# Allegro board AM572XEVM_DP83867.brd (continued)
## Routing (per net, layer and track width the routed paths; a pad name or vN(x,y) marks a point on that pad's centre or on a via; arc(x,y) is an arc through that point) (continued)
TDOR: length 6.8
  TOP w0.12: U11.F19 v2(63.39,33.61)
  GND_L9 w0.094: v1(65.66,29.21) 64.63,30.23 64.63,32.14 64.39,32.38 64.01,32.38 63.76,32.63 63.76,33.23 v2(63.39,33.61)
  BOTTOM w0.12: R61.1 v1(65.66,29.21)
TESTV: length 10.2
  TOP w0.12: v2(61.39,68.01) U5.N12
  SIG_L10 w0.094: TP9.1 53.8,63.32 55.19,64.72 58.1,64.72 v2(61.39,68.01)
TIMER1: length 71.9
  TOP w0.12: U11.E21 v2(61.79,32.81)
  SIG_L5 w0.094: v1(29.21,31.11) 29.72,30.61 31.62,30.61 32.92,29.31 32.92,25.18 32,24.26 32,17.27 32.64,16.64 48.64,16.64 52.32,20.32 52.32,25.15 54.74,27.56 58.04,27.56 59.51,29.03 61.04,29.03 62.14,30.13 62.14,32.45 v2(61.79,32.81)
  BOTTOM w0.12: P17.42 17.99,30.74 18.42,31.16 29.16,31.16 v1(29.21,31.11)
TIMER2: length 67.1
  TOP w0.12: U11.F20 v2(62.59,33.61)
  SIG_L5 w0.094: v1(31.5,30.1) 32.7,28.89 32.7,25.34 31.75,24.38 31.75,17.14 32.51,16.38 48.77,16.38 52.58,20.19 52.58,25.02 54.86,27.3 58.17,27.3 59.67,28.81 61.58,28.81 62.99,30.23 62.99,33.2 v2(62.59,33.61)
  BOTTOM w0.12: P17.13 26.7,29.94 27.05,29.59 29.37,29.59 29.88,30.1 v1(31.5,30.1)
TIMER3: length 65.4
  TOP w0.12: U11.F21 v2(61.79,33.61)
  SIG_L5 w0.094: v2(61.79,33.61) 61.34,33.16 61.34,31.62 60.63,30.92 60.63,29.56 60.33,29.25 59.35,29.25 57.91,27.81 54.61,27.81 52.07,25.27 52.07,20.45 48.51,16.89 32.77,16.89 32.26,17.4 32.26,24.13 33.15,25.02 33.15,29.46 v1(31.5,31.11)
  BOTTOM w0.12: v1(31.5,31.11) 29.88,31.11 29.37,30.61 27.18,30.61 27.05,30.73 22.84,30.73 P17.12
TMP102_ALERT: length 20.2
  TOP w0.12: R15.2 70.04,18.89 U4.3 70.02,20.03 v1(69.22,20.83) ; U11.G17 v2(64.99,34.41)
  GND_L9 w0.094: v1(69.22,20.83) 68.45,21.59 68.45,25.65 67.56,26.54 67.56,33.27 66.81,34.03 65.36,34.03 v2(64.99,34.41)
TMS: length 15.2
  TOP w0.12: U11.F18 v2(64.19,33.61)
  GND_L9 w0.094: v1(65.41,22.35) 66.17,23.11 66.17,29.84 65.41,30.61 65.41,32.88 65.06,33.23 64.56,33.23 v2(64.19,33.61)
  BOTTOM w0.12: P4.1 v1(65.41,22.35)
TPS_ENABLE1: length 16.8
  TOP w0.12: U5.J5 v2(64.59,74.41)
  SIG_L10 w0.094: v2(64.59,74.41) 64.19,74.8 60.93,74.8 60.17,75.56 60.17,79.04 62.69,81.56 62.69,85.42 TP7.1
TPS_PWRDOWN: length 15.5
  TOP w0.12: v2(63.8,71.2) 63.8,71.23 U5.K8
  SIG_L10 w0.094: v2(63.8,71.2) 63.77,71.2 63.41,70.83 61.18,70.83 60.71,70.36 60.71,67.87 58.17,65.33 55.17,65.33 54.2,64.36 TP8.1
TPS_RST: length 3.2
  TOP w0.12: R55.2 R53.1 55.88,9.69 56.04,9.84 U12.1
TRSTN: length 16.9
  TOP w0.12: v1(65.41,20.83) R66.1 ; U11.D20 v2(62.59,32.01)
  GND_L9 w0.094: v2(62.59,32.01) 62.78,32.01 63.76,31.03 63.76,29.2 64.26,28.7 64.26,24.26 64.64,23.88 64.64,21.59 v1(65.41,20.83)
  BOTTOM w0.12: P4.2 v1(65.41,20.83)
TX1+: length 10.7
  BOTTOM w0.127: C449.2 94.31,18.75 94.31,17.87 D29.1 94.07,17.63 94.07,16.04 95.12,14.99 97.16,14.99 97.28,14.86 97.28,14.68 97.41,14.55 97.59,14.55 97.7,14.67 97.7,14.87 97.82,14.99 98.02,14.99 98.13,14.87 98.13,14.67 98.25,14.55 98.42,14.55 98.55,14.68 98.55,15.25 98.7,15.39 98.91,15.39 99.38,14.92 P15.9
TX1-: length 10.7
  BOTTOM w0.127: C448.2 94.67,18.75 94.67,17.87 D29.2 94.91,17.63 94.91,15.7 95.27,15.34 98.15,15.34 98.55,15.75 100.68,15.75 P15.8
TX2+: length 4.5
  TOP w0.127: C451.2 100.09,22.09 100.09,20.09 D31.1 100.33,19.85 100.33,18.95 P15.18
TX2-: length 4.5
  TOP w0.127: P15.17 100.68,18.95 100.68,19.85 D31.2 100.92,20.09 100.92,22.09 C450.2
TX+: length 7.2
  TOP w0.127: C447.2 85.94,18.92 85.94,16.92 86.18,16.67 86.18,16.48 86.06,16.36 83.52,16.36 83.18,16.02 83.18,15.75 P13.9
TX-: length 7.2
  TOP w0.127: P13.8 83.54,15.75 83.54,15.87 83.66,16 86.2,16 86.54,16.34 86.54,16.67 86.78,16.92 86.78,18.92 C446.2
TXN_MUXC: length 3
  TOP w0.102: C457.1 78.23,80.43 77.97,80.17 77.97,79.9 78.52,79.34 78.52,78.24 U31.17
TXP_MUXC: length 3
  TOP w0.102: U31.18 78.17,78.24 78.17,79.19 77.61,79.75 77.61,80.17 77.34,80.43 C454.2
U1-1: length 11.4
  TOP w0.381: U1.1 v1(27.43,67.31)
  INT_L3 w0.381: v1(27.43,67.31) 33.78,67.31 v1(34.54,68.07)
  BOTTOM w0.381: C1.2 33.91,66.42 33.91,67.06 34.54,67.69 v1(34.54,68.07)
U1-3: length 4.2
  TOP w0.381: U1.3 28.07,64.77 27.69,65.15 v1(27.43,65.15)
  BOTTOM w0.381: R3.2 29.05,65.94 28.83,65.72 28.32,65.72 28.1,65.5 R6.1 v1(27.43,65.15)
U1-4: length 3
  TOP w0.381: U1.4 27.69,63.5 27.43,63.75 v1(27.43,64.26)
  BOTTOM w0.254: v1(27.43,64.26) C4.1
U1-8: length 1.8
  BOTTOM w0.381: C1.1 35.31,66.93 35.69,67.31 v1(36.07,67.31)
U2-6: length 2.1
  TOP w0.254: v1(43.18,67.31) 42.93,67.56 U2.6
  BOTTOM w0.381: C10.1 v1(43.18,67.31)
U3-1: length 13.8
  TOP w0.381: U3.1 v1(25.02,81.15)
  INT_L3 w0.381: v1(25.02,81.15) 29.89,81.15 33.78,77.26 v1(33.78,76.83)
  BOTTOM w0.381: C7.2 34.04,77.09 v1(33.78,76.83)
U3-8: length 4.5
  TOP w0.381: v1(33.43,81.73) 33.43,82.33 33.65,82.55 L2.1 35.13,82.55
  BOTTOM w0.381: C7.1 34.04,81.29 33.66,81.67 33.48,81.67 v1(33.43,81.73)
U5_C8: length 3.2
  TOP w0.12: v2(70.19,71.21) U5.C8
  BOTTOM w0.12: C25.2 72.32,71.6 70.58,71.6 v2(70.19,71.21)
U13-4: length 4.2
  TOP w0.12: U13.4 49.96,66.04 49.56,66.45 v1(49.56,67.84)
  BOTTOM w0.12: v1(49.56,67.84) C112.1
U16_FB: length 4.3
  BOTTOM w0.12: U16.8 R203.1 106.21,37.71 106.32,37.59 107.04,37.59 107.15,37.47 R201.2
U17_A17: length 2.3
  TOP w0.12: v1(93.47,35.31) 93.22,35.31 92.96,35.05 U17.40
  BOTTOM w0.12: v1(93.47,35.31) 93.22,35.05 R207.2
U17_A41: length 1.9
  TOP w0.12: v1(91.69,35.31) 91.96,35.04 U17.42
  BOTTOM w0.12: R209.2 v1(91.69,35.31)
U28_1: length 11.2
  TOP w0.381: U28.1 v1(98.68,45.09)
  SIG_L5 w0.381: v1(105.66,45.85) 99.44,45.85 v1(98.68,45.09)
  BOTTOM w0.381: C401.2 105.03,44.2 105.03,44.83 105.66,45.47 v1(105.66,45.85)
U28_3: length 4
  TOP w0.381: v1(98.68,42.55) U28.3
  BOTTOM w0.381: R294.2 100.3,41.69 100.08,41.91 99.57,41.91 99.35,42.13 R297.1 v1(98.68,42.55)
U28_4: length 2.6
  TOP w0.381: U28.4 99.54,41.27 v1(98.68,40.41)
  BOTTOM w0.254: v1(98.68,40.41) C408.1
U28_6: length 3.6
  TOP w0.381: U28.6 107.19,42.55 107.35,42.71 C409.2 R295.1
U28_8: length 1.8
  BOTTOM w0.381: v1(107.19,45.09) 106.81,45.09 106.43,44.7 C401.1
U28_RC: length 1.3
  TOP w0.381: R295.2 C410.1
U29_7: length 3.9
  TOP w0.12: R293.2 102.71,29.98 102.83,30.1 v1(103.63,30.1)
  BOTTOM w0.12: U29.7 104.26,28.44 104.39,28.57 104.39,29.34 v1(103.63,30.1)
U30_7: length 3.9
  TOP w0.12: R298.1 102.71,35.06 102.83,35.18 v1(103.63,35.18)
  BOTTOM w0.12: v1(103.63,35.18) 104.39,34.42 104.39,33.66 104.26,33.52 U30.7
U31_1V8: length 11.4
  TOP w0.254: v1(80.14,74.3) 79.35,74.3 79.09,74.55 U31.9 ; U31.19 77.59,78.86 v1(77.72,78.99) ; U31.13 80.64,76.83 80.65,76.83 80.65,76.08 80.39,75.83 U31.11 ; U31.26 75.44,76.83 75.69,76.58 v1(75.69,76.33) 75.69,76.08 75.44,75.83 U31.28
  TOP w0.381: 80.64,76.83 80.65,76.82 L21.1 v1(83.3,76.82)
  BOTTOM w0.254: C421.1 75.62,76.4 v1(75.69,76.33)
  BOTTOM w0.381: R303.1 75.97,77.31 C421.1
U31_VDD: length 1.2
  TOP w0.381: L21.3 R302.1
U32_ADJ: length 4.5
  BOTTOM w0.12: U32.4 C443.1 R397.1 114.59,48.23 114.68,48.32 115.42,48.32 115.54,48.44 R396.2
UART1_RXD: length 83.8
  TOP w0.12: U11.C26 v2(57.79,31.21)
  SIG_L10 w0.094: v1(116.71,17.14) 112.39,12.82 112.39,10.29 110.74,8.64 78.63,8.64 76.45,10.82 76.45,20.57 73.91,23.11 70.87,23.11 65.15,28.83 65.15,30.51 64.56,31.09 64.56,31.45 64.39,31.62 58.2,31.62 v2(57.79,31.21)
  BOTTOM w0.12: P18.60 115.91,16.34 116.71,17.14 v1(116.71,17.14)
UART1_TXD: length 85.8
  TOP w0.12: U11.B27 v2(56.99,30.41)
  SIG_L10 w0.094: v2(56.99,30.41) 57.41,30.83 64.26,30.83 64.9,30.19 64.9,28.7 70.74,22.86 73.41,22.86 75.97,20.29 75.97,10.64 78.36,8.26 110.87,8.26 112.78,10.16 112.78,12.7 116.59,16.51 117.61,16.51 v1(118.24,17.14)
  BOTTOM w0.12: v1(118.24,17.14) 118.24,17.14 119.04,16.34 P18.30
UART3_RXD: length 42.2
  TOP w0.12: U11.D27 v2(56.99,32.01) ; v1(32.39,36.83) 32.14,36.58 U20.6
  SIG_L5 w0.094: v2(56.99,32.01) 56.61,32.38 51.94,32.38 46.99,27.43 41.28,27.43 40.53,26.69 40.53,24.53 40.26,24.26 35.31,24.26 34.93,24.63 34.93,28.06 34.67,28.32 34.67,29.21 34.93,29.47 34.93,32.12 34.54,32.51 34.54,34.67 v1(32.39,36.83)
UART3_TXD: length 40.3
  TOP w0.12: U20.5 v1(32.37,36.08) ; U11.C28 v2(56.19,31.21)
  SIG_L5 w0.094: v1(32.37,36.08) 34.16,34.29 34.16,24.51 34.92,23.75 40.64,23.75 41.4,24.51 41.4,26.04 42.29,26.92 47.24,26.92 51.53,31.21 v2(56.19,31.21)
UART8_CTSN: length 69.1
  TOP w0.12: U11.G16 v2(65.79,34.41)
  SIG_L5 w0.094: v2(65.79,34.41) 65.41,34.03 60.82,34.03 60.58,33.78 60.58,31.88 60.33,31.62 59.94,31.62 59.74,31.42 59.74,31.06 59.44,30.76 58.44,30.76 58.17,30.48 58.17,29.08 57.4,28.32 54.36,28.32 51.56,25.53 51.56,20.7 48.26,17.4 34.42,17.4 33.3,18.52 33.3,24.41 33.66,24.77 33.66,29.97 v1(31.5,32.13)
  BOTTOM w0.12: P17.11 26.84,31.54 26.92,31.62 29.37,31.62 29.88,32.13 v1(31.5,32.13)
UART8_RTSN: length 67.8
  TOP w0.12: U11.D17 v2(64.99,32.01)
  SIG_L5 w0.094: v1(31.5,29.08) 32.26,28.32 32.26,25.65 31.24,24.64 31.24,16.89 32.26,15.88 49.02,15.88 53.09,19.94 53.09,24.38 54.32,25.62 58.01,25.62 58.8,26.42 58.8,27.18 59.94,28.32 61.85,28.32 62.36,28.83 64.01,28.83 64.56,29.38 64.56,31.58 v2(64.99,32.01)
  BOTTOM w0.12: P17.14 26.49,29.14 27.05,28.57 29.37,28.57 29.88,29.08 v1(31.5,29.08)
UART8_RXD: length 72.6
  TOP w0.12: U11.C18 v2(64.19,31.21)
  SIG_L5 w0.094: v2(64.19,31.21) 63.83,30.85 63.83,29.54 63.37,29.08 62.23,29.08 61.72,28.57 59.82,28.57 58.55,27.3 58.55,26.54 57.85,25.84 54.23,25.84 52.83,24.44 52.83,20.07 48.89,16.13 32.39,16.13 31.5,17.02 31.5,24.51 32.48,25.5 32.48,28.73 31.62,29.59 29.72,29.59 v1(29.21,30.1)
  BOTTOM w0.12: P17.43 18.03,29.94 18.44,30.36 26.79,30.36 27.05,30.1 v1(29.21,30.1)
UART8_TXD: length 55.3
  TOP w0.12: U11.A21 61.26,29.08 58.93,29.08 57.18,27.34 57.18,24.16 v1(56.52,23.5)
  SIG_L10 w0.094: v1(56.52,23.5) 56.11,23.9 54.76,23.9 54.1,23.24 54.1,18.54 50.29,14.73 25.34,14.73 v1(21.34,18.74)
  BOTTOM w0.12: P17.27 v1(21.34,18.74)
UART9_CTSN: length 98
  TOP w0.12: U11.AB3 v2(76.99,47.21)
  SIG_L5 w0.094: v2(76.99,47.21) 76.61,46.83 70.43,46.83 70.16,47.09 70.16,52.39 69.6,52.96 55.12,52.96 52.2,55.88 52.2,57.76 47.47,62.48 36.45,62.48 33.53,59.56 33.53,45.85 31.24,43.56 31.24,35.18 v1(29.21,33.15)
  BOTTOM w0.12: v1(29.21,33.15) 27.59,33.15 26.7,34.04 25.53,34.04 24.26,32.77 18.42,32.77 17.99,32.34 P17.40
UART9_RTSN: length 97.7
  TOP w0.12: U11.AA4 v2(76.19,46.41)
  SIG_L5 w0.094: v1(31.5,34.16) 31.5,43.43 33.78,45.72 33.78,59.44 36.58,62.23 47.35,62.23 51.82,57.76 51.82,55.88 54.99,52.7 68.96,52.7 69.36,52.3 69.36,46.29 69.68,45.98 75.57,45.98 76,46.41 v2(76.19,46.41)
  BOTTOM w0.12: P17.39 18.03,33.14 18.42,33.53 24,33.53 25.02,34.54 27.05,34.54 27.18,34.67 29.34,34.67 29.84,34.16 v1(31.5,34.16)
UART9_RXD: length 93.8
  TOP w0.12: U11.AA3 v2(76.99,46.41)
  SIG_L5 w0.094: v1(31.5,33.15) 32,33.66 32,34.54 31.75,34.8 31.75,43.31 34.04,45.59 34.04,59.31 36.7,61.98 47.24,61.98 51.31,57.91 51.31,55.96 54.81,52.45 68.33,52.45 68.58,52.2 68.58,45.47 68.83,45.21 74.8,45.21 75.31,45.72 75.77,45.72 76.03,45.98 76.34,45.98 76.76,46.41 v2(76.99,46.41)
  BOTTOM w0.12: v1(31.5,33.15) 29.88,33.15 29.37,32.64 27.08,32.64 26.48,32.03 25.37,32.03 25.06,32.34 P17.10
UART9_TXD: length 84.9
  TOP w0.12: U11.AB9 v2(72.19,47.21)
  SIG_L5 w0.094: v1(29.21,34.16) 30.99,35.94 30.99,43.69 33.27,45.97 33.27,59.69 36.32,62.74 47.6,62.74 52.58,57.76 52.58,55.88 55.25,53.21 69.98,53.21 70.87,52.32 70.87,49.4 70.99,49.28 70.99,47.86 71.23,47.62 71.5,47.62 71.92,47.21 v2(72.19,47.21)
  BOTTOM w0.12: P17.9 24.12,33.14 25.27,34.29 27.47,34.29 27.59,34.16 v1(29.21,34.16)
UART10_CTSN: length 46
  TOP w0.12: U11.D2 v2(77.79,32.01)
  SIG_L5 w0.094: v2(77.79,32.01) 78.21,31.58 78.21,31.01 78.44,30.78 78.74,30.78 79.3,30.23 85.85,30.23 87,29.08 98.04,29.08 98.42,29.46 116.05,29.46 116.22,29.63 116.22,30.12 116.59,30.48 118.59,30.48 v1(119.13,29.94)
  BOTTOM w0.12: P18.13 v1(119.13,29.94)
UART10_RTSN: length 48.8
  TOP w0.12: U11.F4 v2(76.19,33.61)
  SIG_L5 w0.094: v1(118.24,34.74) 117.28,33.78 109.35,33.78 106.3,36.83 97.92,36.83 97.79,36.7 84.07,36.7 83.75,36.38 78.42,36.38 78.16,36.13 78.16,35.85 77.94,35.63 77.66,35.63 77.36,35.33 77.36,34.95 76.19,33.77 v2(76.19,33.61)
  BOTTOM w0.12: v1(118.24,34.74) 118.24,34.74 119.04,33.94 P18.8
UART10_RXD: length 44.3
  TOP w0.12: U11.D1 v2(78.59,32.01)
  SIG_L5 w0.094: v2(78.59,32.01) 79.1,31.49 79.1,31.33 79.57,30.86 99.31,30.86 99.72,31.26 113.52,31.26 114.17,30.61 116.33,30.61 116.71,30.99 117.69,30.99 v1(118.24,31.54)
  BOTTOM w0.12: v1(118.24,31.54) 119.04,30.74 P18.12
UART10_TXD: length 43.7
  TOP w0.12: U11.E2 v2(77.79,32.81)
  SIG_L5 w0.094: v2(77.79,32.81) 78.21,32.38 78.87,32.38 79.35,31.9 82.91,31.9 83.69,31.11 99.19,31.11 99.57,31.5 113.79,31.5 114.43,30.86 116.21,30.86 116.71,31.37 v1(116.71,31.54)
  BOTTOM w0.12: v1(116.71,31.54) 115.91,30.74 P18.42
USB1_DM: length 48.4
  TOP w0.127: v3(86.49,33.02) 86.75,32.75 86.75,31.97 87.55,31.17 88.17,31.17 88.22,31.11 88.24,31.11 88.27,31.09 ; U11.AC12 v3(69.79,48.01)
  INT_L3 w0.114: v3(81.15,55.5) 82.93,55.5 85.34,53.09 85.34,34.28 86.49,33.13 v3(86.49,33.02)
  SIG_L10 w0.114: v3(69.79,48.01) 70.17,48.39 70.17,53.66 73.83,57.32 78.96,57.32 80.64,55.63 81.02,55.63 v3(81.15,55.5)
USB1_DP: length 48.5
  TOP w0.127: 88.27,31.6 88.19,31.52 87.7,31.52 87.11,32.11 87.11,33.03 v3(86.49,33.66) ; U11.AD12 v3(69.79,48.81)
  INT_L3 w0.114: v3(86.49,33.66) 85.71,34.43 85.71,53.24 83.08,55.87 81.42,55.87 v3(81.15,56.13)
  SIG_L10 w0.114: v3(69.79,48.81) 69.42,49.17 69.42,52.15 69.81,52.53 69.81,53.82 73.67,57.68 79.11,57.68 79.32,57.47 80.79,56 81.02,56 v3(81.15,56.13)
USB1_DRVBUS_R: length 39.3
  TOP w0.12: U11.AB10 v2(71.39,47.21) ; R330.1 87.6,36.29 87.38,36.07 v1(87.38,34.29)
  GND_L9 w0.094: v1(81.79,47.24) 81.28,47.75 79.5,47.75 78.87,48.39 78.3,48.39 77.54,47.62 73.61,47.62 73.38,47.4 73.38,47.02 73.22,46.85 71.74,46.85 v2(71.39,47.21)
  BOTTOM w0.12: v1(81.79,47.24) 82.8,46.23 82.8,31.37 83.44,30.73 86.61,30.73 86.96,31.08 86.96,33.87 v1(87.38,34.29)
USB1_DRVVBUS: length 1.8
  TOP w0.254: U17.48 88.96,35.28 R329.2
  TOP w0.381: R330.2 R329.2
USB1_ID: length 3.5
  TOP w0.12: U11.C27 v2(56.99,31.21)
  BOTTOM w0.12: v2(56.99,31.21) 57.39,30.81 57.39,29.23 57.66,28.96 R205.1
USB1V:
  vias: v1(105.03,26.67) v1(105.79,26.67)
USB1VBUS: length 39.9
  SIG_L10 w0.381: P13.1 82.08,13.43 81.28,14.22 81.28,16 87.25,21.97 v1(110.83,21.97)
  BOTTOM w0.381: D35.1 82.8,13.37 P13.1 ; L18.2 v1(110.83,21.97)
USB2_5V: length 11.5
  BOTTOM w0.381: R412.1 R320.1 92.74,8.03 C479.1 92.55,8.16 R31.1 D42.1 88.89,7.1 87.66,5.87 P7.1
USB2_DM: length 67.2
  TOP w0.127: U11.AF11 v3(70.59,50.41)
  INT_L3 w0.114: v3(86.87,9.78) 86.8,9.84 86.8,10.87 85.88,11.8 83.21,11.8 81.53,13.47 81.53,15.48 83.3,17.25 83.3,29.69 83.86,30.25 83.86,52.59 81.85,54.6 81.29,54.6 v3(81.15,54.74)
  SIG_L10 w0.114: v3(70.59,50.41) 70.99,50.81 70.99,52.59 74.61,56.21 78.41,56.21 80,54.62 81.04,54.62 v3(81.15,54.74)
  BOTTOM w0.127: R211.1 86.87,9.36 v3(86.87,9.78)
USB2_DMEX: length 92.5
  INT_L3 w0.114: v3(117.86,59.05) 117.66,58.85 117.66,58.63 121.92,54.37 121.92,10.53 120.17,8.78 92.05,8.78 90.5,10.33 89.83,10.33 89.67,10.17 89.67,9.55 89.57,9.45 89.43,9.45 89.33,9.55 89.33,10.22 89.23,10.33 89.09,10.33 88.99,10.22 88.99,9.55 88.89,9.45 88.75,9.45 88.64,9.55 88.64,10.16 88.48,10.33 88.19,10.33 88.07,10.21 v3(88.07,9.78)
  BOTTOM w0.127: P16.29 v3(117.86,59.05) ; R315.2 v3(88.07,9.78)
USB2_DP: length 67.1
  TOP w0.127: U11.AE11 v3(70.59,49.61)
  INT_L3 w0.114: v3(81.15,54.1) 81.28,54.23 81.66,54.23 83.49,52.4 83.49,30.4 82.93,29.84 82.93,17.4 81.17,15.63 81.17,13.32 83.06,11.43 85.72,11.43 85.9,11.25 85.9,11 86.06,10.85 86.31,10.85 86.44,10.72 86.44,9.86 v3(86.36,9.78)
  SIG_L10 w0.114: v3(81.15,54.1) 81,54.25 79.84,54.25 78.26,55.84 74.76,55.84 71.36,52.44 71.36,50.66 70.84,50.14 70.84,49.86 v3(70.59,49.61)
  BOTTOM w0.127: v3(86.36,9.78) 86.36,9.36 R210.1
USB2_DPEX: length 92.4
  INT_L3 w0.114: v3(117.09,59.05) 117.29,58.85 117.29,58.48 121.55,54.22 121.55,10.68 120.02,9.14 92.2,9.14 90.65,10.69 88.03,10.69 87.7,10.36 87.7,9.73 87.25,9.27 86.23,9.27 85.69,9.81 v3(85.47,9.81)
  BOTTOM w0.127: R314.2 85.16,9.49 v3(85.47,9.81) ; P16.59 v3(117.09,59.05)
USB2_DRVBUS: length 104.3
  TOP w0.12: U11.AC10 v2(71.39,48.01)
  SIG_L5 w0.381: v1(18.03,17.14) 20.45,17.14 24.83,12.76 41.34,12.76 41.73,13.15 61.49,13.15 62.79,14.45 75.21,14.45 76.2,15.44 76.2,24.38 77.72,25.91 v1(77.72,26.92)
  SIG_L10 w0.381: v1(77.72,26.92) 77.72,27.18 80.7,30.15 82.04,30.15 83.06,31.17 83.06,32.51 87.63,37.08 v1(88.14,37.08)
  BOTTOM w0.381: v1(88.14,37.08) 88.39,37.34 88.39,45.59 v1(84.96,49.02) ; P17.59 v1(18.03,17.14)
USB2_ID: length 53.2
  TOP w0.12: U11.E25 v2(58.59,32.81)
  SIG_L5 w0.094: v1(49.02,20.07) 51.05,22.1 51.05,25.77 55.64,30.35 56.26,30.35 56.76,30.85 57.14,30.85 57.34,31.05 57.34,31.3 57.59,31.56 57.84,31.56 58.17,31.89 58.17,32.38 v2(58.59,32.81)
  SIG_L8 w0.094: v1(49.02,20.07) 49.02,19.54 47,17.53 34.42,17.53 33.89,18.06 26.27,18.06 v1(25.78,18.54)
  BOTTOM w0.12: R321.2 56.77,29.08 56.59,29.27 56.59,32.17 56.82,32.41 58.19,32.41 v2(58.59,32.81) ; v1(25.78,18.54) 24.89,17.65 24.89,17.02 24.21,16.34 P17.30
USB2_OC: length 48.4
  TOP w0.12: U11.B24 v2(59.39,30.41)
  SIG_L8 w0.094: v1(21.28,17.14) 21.53,16.89 47.37,16.89 51.31,20.83 51.31,24 57.4,30.1 57.4,30.61 57.58,30.78 59.01,30.78 59.38,30.41 v2(59.39,30.41)
  BOTTOM w0.12: P17.29 v1(21.28,17.14)
USB2_VBUS: length 78.8
  TOP w0.12: v2(69.39,71.21) U5.D8
  INT_L3 w0.094: v1(87,54.56) 87,22.23 92.46,16.76 v1(92.46,14.48)
  SIG_L5 w0.094: v2(69.39,71.21) 69.39,71.2 70.61,69.98 70.61,69.47 70.87,69.22 71.12,69.22 71.37,68.96 71.37,67.12 72.01,66.49 72.01,64.9 78.11,58.8 78.74,58.8 80.77,56.77 84.79,56.77 v1(87,54.56)
  BOTTOM w0.12: R412.2 96.27,9.4 95,10.67 95,11.94 v1(92.46,14.48) ; v2(69.39,71.21) 69.38,71.21 69,71.59 69,72.23 68.45,72.77 R411.1
USB2V:
  vias: v1(105.03,30.48) v1(105.79,30.48)
USB2VBUS: length 27.9
  SIG_L10 w0.381: v1(111.63,18.8) 111.63,15.88 110.36,14.61 109.6,14.61 107.44,12.45 100.98,12.45 P15.1
  BOTTOM w0.381: v1(111.63,18.8) D34.1 112.15,19.82 112.39,20.07 112.39,21.45 112.1,21.74 112.1,21.76 112.01,21.84 112.01,28.19 111.63,28.57 L17.2
USB2VBUS_EXP: length 87.7
  SIG_L5 w0.094: v1(18.03,16.34) 20.49,16.34 24.64,12.19 76.71,12.19 77.72,13.21 81.03,13.21 82.04,12.19 90.42,12.19 91.95,13.72 v1(92.46,13.72)
  BOTTOM w0.12: P17.60 v1(18.03,16.34) ; R320.2 95.25,9.4 95,9.65 92.2,9.65 91.19,10.67 91.19,12.45 v1(92.46,13.72)
USB3V:
  vias: v1(107.19,30.48) v1(107.95,30.48)
USB3VBUS: length 34.3
  SIG_L8 w0.381: P15.10 100.46,17.08 100.46,18.77 101.88,20.19 111.63,20.19 112.65,21.21 v1(112.65,21.97)
  BOTTOM w0.381: P15.10 99.2,16.63 98.5,17.32 98.5,18.49 99.96,19.95 D36.1 ; v1(112.65,21.97) 112.65,31.5 111.76,32.38 L19.2
USB4V: length 116.8
  SIG_L10 w0.762: v1(109.22,39.12) 112.39,42.29 112.39,44.83 113.92,46.35 119.76,46.35 121.54,48.13 121.54,86.74 118.11,90.17 110.36,90.17 109.6,90.93 109.6,95 107.75,96.85 90.98,96.85 86.36,101.47 80.52,101.47 v1(79.63,102.36) v1(79.63,103)
  BOTTOM w0.762: v1(109.22,39.12) 109.22,37.72 v1(105.79,34.29) ; v1(79.63,103) 80.73,103 L20.1 80.69,102.36 v1(79.63,102.36)
  vias: v1(105.03,34.29)
USB4VBUS: length 4.5
  BOTTOM w0.381: L20.2 81.37,101.1 D37.1
  BOTTOM w1.27: P6.1 80.97,100.7 L20.2
USB_5V: length 40.9
  TOP w0.381: R292.1 111.51,41.27 112.39,42.16 112.39,46.48 L16.2 ; C403.1 103.86,51.05 103.48,50.67 103.48,50.64 v1(103.45,50.61)
  INT_L3 w0.381: v1(103.45,50.61) 103.48,50.58 103.48,48.24 99.31,44.07 99.31,34.42 99.82,33.91 v1(99.82,33.02)
  SIG_L8 w0.381: v1(99.57,28.7) 99.19,29.08 99.19,32.38 v1(99.82,33.02)
  BOTTOM w0.305: U30.2 99.94,32.52 99.82,32.64 v1(99.82,33.02) U30.3 ; v1(99.57,28.7) 99.57,28.19 99.82,27.94 ; 99.82,27.94 99.82,27.56 99.94,27.44 U29.2 ; 99.82,27.94 U29.3
USB_DM0: length 24.2
  TOP w0.127: P13.2 86.18,12.6 86.18,12.4 85.98,12.19 82.55,12.19 81.41,13.34 81.41,15.49 83.08,17.17 83.93,17.17 84.87,18.11 84.87,19.79 D27.1 84.63,20.03 84.63,20.63 86.99,22.99 87.15,22.99 87.25,22.89 87.4,22.89 87.52,23 87.52,23.16 87.42,23.26 87.42,23.41 87.53,23.53 87.69,23.53 87.78,23.43 87.94,23.43 88.05,23.54 88.05,23.7 87.96,23.79 87.96,23.95 88.16,24.16 88.92,24.16 89.39,24.62 89.39,25.33 U17.2
USB_DM1: length 25.1
  TOP w0.127: v3(93.51,24.64) 93.39,24.76 93.39,25.33 U17.10
  BOTTOM w0.127: v3(93.51,24.64) 93.39,24.51 93.39,23.92 93.01,23.55 93.01,17.87 D30.2 93.26,17.63 93.26,16.08 93.01,15.84 93.01,15.44 94.74,13.72 97.66,13.72 99.44,11.94 101.25,11.94 101.36,12.05 101.36,12.28 101.47,12.4 101.63,12.4 101.74,12.28 101.74,12.05 101.85,11.94 102.01,11.94 102.12,12.05 102.12,12.28 102.23,12.4 102.39,12.4 102.5,12.28 102.5,12.05 102.62,11.94 102.87,11.94 103.3,12.37 103.3,12.63 P15.2
USB_DM2: length 24.5
  TOP w0.127: U17.18 97.23,26.52 97.8,26.52 98,26.33 98.15,26.33 98.25,26.43 98.41,26.43 98.52,26.32 98.52,26.16 98.42,26.06 98.42,25.9 98.6,25.73 98.6,21.88 98.84,21.64 98.84,20.09 D33.2 98.6,19.85 98.6,13.16 99.57,12.19 102.49,12.19 103.33,13.03 103.33,13.89 102.5,14.72 P15.11
USB_DM3: length 92.7
  TOP w0.127: v3(97.92,30.23) 97.78,30.09 U17.25
  INT_L3 w0.114: v3(97.92,30.23) 98.33,30.23 98.44,30.34 98.44,30.53 98.33,30.65 94.32,30.65 91.68,33.29 91.68,33.91 90.18,35.41 90.18,37.06 88.27,38.98 88.27,57.68 80.91,65.04 80.91,81.34 82.39,82.82 82.39,99.37 81.28,100.48 81.09,100.48 80.81,100.2 80.65,100.2 80.54,100.31 80.54,100.47 80.84,100.77 80.84,100.9 80.73,101.01 80.56,101.01 80.26,100.71 80.14,100.71 80.01,100.84 80.01,100.97 80.31,101.27 80.31,101.42 80.23,101.51 79.21,101.51 78.49,102.23 77.79,102.23 77.64,102.08 77.64,101.78 v3(77.82,101.6)
  BOTTOM w0.127: v3(77.82,101.6) D32.2 77.89,100.94 77.89,98.93 P6.2
USB_DP0: length 24.2
  TOP w0.127: P13.3 86.54,12.6 86.54,12.25 86.13,11.84 82.4,11.84 81.05,13.19 81.05,15.64 82.94,17.53 83.78,17.53 84.04,17.78 84.04,19.79 D27.2 84.28,20.03 84.28,20.78 88.01,24.51 88.77,24.51 89.03,24.77 89.03,25.33 U17.1
USB_DP1: length 24.9
  TOP w0.127: v3(92.9,24.64) 93.03,24.77 93.03,25.33 U17.9
  BOTTOM w0.127: 104.51,13.43 103.66,12.58 103.66,12.22 103.02,11.58 99.29,11.58 97.51,13.36 94.59,13.36 92.66,15.3 92.66,15.84 92.42,16.08 92.42,17.63 D30.1 92.66,17.87 92.66,23.7 93.03,24.07 93.03,24.51 v3(92.9,24.64)
USB_DP2: length 24.6
  TOP w0.127: 104.51,16.63 104.51,14.74 103.68,13.91 103.68,12.87 102.64,11.84 99.42,11.84 98.25,13.01 98.25,19.85 D33.1 98.01,20.09 98.01,21.64 98.25,21.88 98.25,25.58 97.66,26.17 97.23,26.17 U17.17
USB_DP3: length 92.8
  TOP w0.127: v3(97.92,29.46) 97.78,29.6 U17.24
  INT_L3 w0.114: v3(97.92,29.46) 98.45,29.46 98.78,29.8 98.78,30.67 98.47,30.99 96.74,30.99 96.72,31.01 94.48,31.01 92.05,33.44 92.05,34.06 90.55,35.56 90.55,37.21 88.63,39.13 88.63,57.84 81.28,65.19 81.28,81.19 82.76,82.67 82.76,99.49 80.39,101.85 80.08,101.85 79.39,101.85 78.85,102.39 78.64,102.6 78.02,102.6 77.64,102.6 77.27,102.23 77.27,101.75 v3(77.12,101.6)
  BOTTOM w0.127: v3(77.12,101.6) D32.1 77.05,100.94 77.05,98.93 P6.3
USB_R1: length 1.5
  TOP w0.12: 88.27,26.1 86.9,26.1 R206.2
USB_RXM0: length 12
  TOP w0.127: U17.7 91.89,25.33 91.89,23.19 89.54,20.84 89.54,18.84 89.78,18.6 89.78,16.92 89.54,16.67 89.54,15.75 P13.5
USB_RXM1: length 23.9
  TOP w0.127: v3(96.01,24.64) 95.89,24.76 95.89,25.33 U17.15
  BOTTOM w0.127: v3(96.01,24.64) 95.89,24.51 95.89,24.12 96.39,23.62 96.64,23.62 96.75,23.73 96.75,23.97 96.87,24.08 97.02,24.08 97.13,23.97 97.13,23.73 97.25,23.62 97.4,23.62 97.52,23.73 97.52,23.97 97.63,24.08 97.78,24.08 97.9,23.97 97.9,23.73 98.01,23.62 106.69,23.62 108.64,21.67 108.64,21.04 D28.2 108.88,20.8 108.88,19.18 108.68,18.98 108.68,16.64 107.7,15.65 107.7,15.12 P15.5
USB_RXM2: length 17.7
  TOP w0.127: U17.23 97.23,29.02 98.61,29.02 102.87,24.76 102.87,23.62 103.66,22.83 106.05,22.83 106.68,22.2 106.68,21.88 106.92,21.64 106.92,20.09 D38.2 106.68,19.85 106.68,18.95 P15.14
USB_RXP0: length 12
  TOP w0.127: U17.6 91.53,25.33 91.53,23.33 89.19,20.99 89.19,18.84 88.94,18.59 88.94,16.92 89.18,16.67 89.18,15.75 P13.6
USB_RXP1: length 23.9
  TOP w0.127: v3(95.4,24.64) 95.53,24.77 95.53,25.33 U17.14
  BOTTOM w0.127: v3(95.4,24.64) 95.53,24.51 95.53,23.98 96.24,23.27 106.54,23.27 108.28,21.53 108.28,21.04 D28.1 108.04,20.8 108.04,19.18 108.33,18.89 108.33,16.78 107.29,15.75 106.33,15.75 P15.6
USB_RXP2: length 17.6
  TOP w0.127: P15.15 106.33,18.95 106.33,19.85 D38.1 106.09,20.09 106.09,21.64 106.33,21.88 106.33,22.06 105.91,22.48 105.64,22.48 105.53,22.37 105.53,22.21 105.42,22.1 105.26,22.1 105.15,22.21 105.15,22.37 105.04,22.48 103.51,22.48 102.51,23.47 102.51,24.61 98.46,28.67 97.23,28.67 U17.22
USB_SNS: length 3.2
  TOP w0.381: U28.5 v1(107.25,41.27) R292.2
  BOTTOM w0.381: v1(107.25,41.27) R296.2
USB_SSRXM0: length 1.5
  TOP w0.127: 88.27,28.6 86.98,28.6 C244.2
USB_SSRXP0: length 1.5
  TOP w0.127: 88.27,29.1 86.95,29.1 C239.2
USB_SSTXM0: length 1.5
  TOP w0.127: 88.27,30.09 86.96,30.09 C242.2
USB_SSTXP0: length 1.5
  TOP w0.127: C241.2 86.97,30.59 88.27,30.59
USB_TXM0: length 7.2
  TOP w0.127: U17.4 90.39,25.33 90.39,24.23 86.54,20.38 86.54,20.11 C446.1
USB_TXM1: length 5.9
  TOP w0.127: v3(94.67,24.64) 94.38,24.92 94.38,25.32 U17.12
  BOTTOM w0.127: v3(94.67,24.64) 94.51,24.49 94.51,21.56 94.67,21.41 94.67,20.11 C448.1
USB_TXM2: length 6.9
  TOP w0.127: U17.20 97.23,27.52 98.58,27.52 100.68,25.42 100.68,23.28 C450.1
USB_TXP0: length 7.2
  TOP w0.127: C447.1 86.18,20.11 86.18,20.52 90.03,24.37 90.03,25.33 U17.3
USB_TXP1: length 5.7
  TOP w0.127: U17.11 94.03,25.33 94.03,24.67 v3(94.06,24.64)
  BOTTOM w0.127: C449.1 94.31,20.11 94.31,21.26 94.16,21.41 94.16,24.54 v3(94.06,24.64)
USB_TXP2: length 6.9
  TOP w0.127: C451.1 100.33,23.28 100.33,25.28 99.99,25.61 99.84,25.61 99.68,25.45 99.52,25.45 99.41,25.56 99.41,25.72 99.57,25.88 99.57,26.04 98.44,27.17 97.23,27.17 U17.19
USBSP_DM: length 3.7
  BOTTOM w0.127: P7.2 86.96,4.65 86.96,5.73 87.03,5.8 87.03,7.34 D40.2 86.96,8 R211.2
USBSP_DP: length 3.7
  BOTTOM w0.127: P7.3 86.26,4.7 86.26,5.73 86.19,5.8 86.19,7.34 D40.1 86.26,8 R210.2
USR0: length 34.8
  TOP w0.12: U11.F16 v2(65.79,33.61) ; Q3.2 63.4,5.77 62.92,6.24 R219.1 62.87,6.63 v1(63.25,7.01)
  GND_L9 w0.094: v1(64.13,20.83) 64.64,20.32 66.68,20.32 67.18,20.83 67.18,32.77 66.7,33.25 66.14,33.25 v2(65.79,33.61)
  SIG_L10 w0.094: v1(64.13,20.83) 64.77,20.19 64.77,14.99 64.82,14.94 64.82,8.99 63.25,7.42 v1(63.25,7.01)
USR1: length 29.8
  TOP w0.12: Q3.5 66.14,5.77 66.62,6.24 R220.1 v1(66.68,6.91) ; U11.B25 v2(58.59,30.41)
  SIG_L8 w0.094: v1(66.68,6.91) 66.68,9.68 67.08,10.08 67.08,10.92 63.5,14.5 63.5,23.88 60.71,26.67 60.71,27.46 58.96,29.21 58.96,30.03 v2(58.59,30.41)
USR2: length 37.4
  TOP w0.12: v1(73,7.32) R221.1 73.03,6.65 73.51,6.17 Q4.2 ; U11.A26 v2(57.79,29.61)
  SIG_L8 w0.094: v1(73,7.32) 72.57,6.88 72.54,6.88 71.55,5.89 66.12,5.89 65.48,6.53 65.48,10.06 64.59,10.95 64.59,11.66 63.25,13 63.25,23.75 60.83,26.16 60.45,26.16 59.94,26.67 59.94,27.45 v2(57.79,29.61)
USR3: length 45
  TOP w0.12: U11.B22 v2(60.99,30.41) ; Q4.5 76.28,6.17 76.75,6.65 R222.1 v1(76.81,7.32)
  GND_L9 w0.094: v1(60.33,21.84) 60.71,22.23 60.71,29.08 60.58,29.21 60.58,29.97 60.99,30.38 v2(60.99,30.41)
  SIG_L10 w0.094: v1(60.33,21.84) 60.71,21.46 62.1,21.46 64.39,19.18 64.39,9.12 62.64,7.37 62.64,6.32 62.87,6.1 73.53,6.1 74.32,6.88 76.38,6.88 v1(76.81,7.32)
VBG: length 4.8
  TOP w0.12: v2(70.99,72.01) U5.B7
  SIG_L8 w0.381: v1(74.17,72.39) 73.91,72.64 71.62,72.64 v2(70.99,72.01)
  BOTTOM w0.381: C16.2 v1(74.17,72.39)
VDAC_3V3: length 17
  TOP w0.254: C260.1 55.25,13.34 55.56,13.65 v1(56.01,13.65)
  TOP w0.381: v1(55.75,22.61) L12.3 ; v1(55.75,22.61) v1(55.12,22.61) ; v1(55.75,22.61) 55.75,21.97 55.5,21.72 55.12,21.72 ; 54.48,21.72 53.98,21.21 L15.1 ; 54.48,21.72 55.12,21.72 ; 54.48,21.72 54.45,21.75 C247.1 v1(55.12,22.61) ; U19.1 v1(56.01,13.65) ; 55.12,21.72 v1(55.12,22.61) ; 62.36,21.84 62.87,21.34 L14.1 ; 62.36,21.84 62.39,21.88 C252.1 v1(61.72,22.61) v1(61.72,21.84) 62.36,21.84 ; L13.1 53.98,16.64 ; 53.98,16.64 v1(53.98,17.78) ; 53.98,16.64 54.61,17.27 54.61,17.53 v1(55.12,18.03)
VOUT1_CLK: length 38.5
  SIG_L5 w0.094: v1(115.82,18.74) 114.86,18.74 114.03,19.58 110.22,19.58 109.22,20.57 83.82,20.57 82.36,22.03 81.47,22.03 v1(81.03,22.48)
  BOTTOM w0.12: R149.2 v1(81.03,22.48) ; P18.57 v1(115.82,18.74)
VOUT1_D0: length 38.5
  SIG_L5 w0.094: v1(84.07,23.37) 85.09,22.35 114.68,22.35 115.7,21.34 118.13,21.34 v1(119.13,20.34)
  BOTTOM w0.12: P18.25 v1(119.13,20.34) ; R124.2 v1(84.07,23.37)
VOUT1_D1: length 34.8
  SIG_L5 w0.094: v1(84.07,22.48) 84.45,22.48 84.84,22.1 109.98,22.1 110.49,21.59 114.57,21.59 v1(115.82,20.34)
  BOTTOM w0.12: R125.2 v1(84.07,22.48) ; P18.55 v1(115.82,20.34)
VOUT1_D2: length 37
  SIG_L5 w0.094: v1(84.07,24.26) 84.71,24.26 86.36,22.61 116.05,22.61 v1(116.71,21.94)
  BOTTOM w0.12: P18.54 115.91,21.14 116.71,21.94 v1(116.71,21.94) ; R126.2 v1(84.07,24.26)
VOUT1_D3: length 38.7
  SIG_L5 w0.094: v1(84.07,21.59) 84.58,21.08 109.47,21.08 110.49,20.07 114.68,20.07 115.19,19.56 117.45,19.56 v1(118.24,20.34)
  BOTTOM w0.12: P18.26 119.04,19.54 v1(118.24,20.34) ; R127.2 v1(84.07,21.59)
VOUT1_D4: length 38.6
  SIG_L5 w0.094: v1(116.71,26.74) 116.71,26.29 116.33,25.91 113.41,25.91 111.12,23.62 86.87,23.62 84.45,26.04 v1(84.07,26.04)
  BOTTOM w0.12: P18.48 115.91,25.94 v1(116.71,26.74) ; R128.2 v1(84.07,26.04)
VOUT1_D5: length 35.6
  SIG_L5 w0.094: v1(115.82,25.14) 115.44,24.77 113.54,24.77 111.89,23.11 86.61,23.11 84.58,25.15 v1(84.07,25.15)
  BOTTOM w0.12: P18.49 v1(115.82,25.14) ; R129.2 v1(84.07,25.15)
VOUT1_D6: length 35.9
  SIG_L5 w0.094: v1(115.82,28.34) 110.38,28.34 108.2,26.16 99.7,26.16 98.17,27.69 90.3,27.69 89.66,28.32 86.61,28.32 86.23,28.7 v1(84.07,28.7)
  BOTTOM w0.12: R130.2 v1(84.07,28.7) ; P18.45 v1(115.82,28.34)
VOUT1_D7: length 38.6
  SIG_L5 w0.094: v1(84.07,27.81) 84.45,27.81 84.84,28.19 85.98,28.19 86.36,27.81 89.41,27.81 90.04,27.18 97.92,27.18 99.44,25.65 110.62,25.65 112.65,27.69 116.46,27.69 116.71,27.94 v1(116.71,28.34)
  BOTTOM w0.12: v1(116.71,28.34) 116.71,28.34 115.91,27.54 P18.46 ; R131.2 v1(84.07,27.81)
VOUT1_D8: length 36.1
  SIG_L5 w0.094: v1(84.07,26.92) 84.33,26.92 87.12,24.13 110.36,24.13 112.97,26.74 v1(115.82,26.74)
  BOTTOM w0.12: R132.2 v1(84.07,26.92) ; P18.47 v1(115.82,26.74)
VOUT1_D9: length 41.1
  SIG_L5 w0.094: v1(81.03,24.26) 81.15,24.26 81.6,23.81 82.04,23.81 83.86,21.99 84.43,21.99 84.58,21.84 109.09,21.84 110.62,20.32 114.94,20.32 115.44,19.81 116.19,19.81 v1(116.71,20.34)
  BOTTOM w0.12: R133.2 v1(81.03,24.26) ; v1(116.71,20.34) 115.91,19.54 P18.56
VOUT1_D10: length 43
  SIG_L5 w0.094: v1(118.24,28.34) 117.33,27.43 113.03,27.43 110.74,25.15 86.49,25.15 84.26,27.37 81.6,27.37 81.15,27.81 v1(81.03,27.81)
  BOTTOM w0.12: R134.2 v1(81.03,27.81) ; v1(118.24,28.34) 118.24,28.34 119.04,27.54 P18.16
VOUT1_D11: length 43.1
  SIG_L5 w0.094: v1(118.24,26.74) 117.04,25.54 113.68,25.54 111.51,23.37 86.74,23.37 84.52,25.59 81.6,25.59 81.15,26.04 v1(81.03,26.04)
  BOTTOM w0.12: P18.18 119.04,25.94 v1(118.24,26.74) ; R135.2 v1(81.03,26.04)
VOUT1_D12: length 47.1
  TOP w0.12: R136.2 v1(76.96,26.92)
  SIG_L10 w0.094: v1(118.24,25.14) 117.72,25.65 88.27,25.65 85.66,28.26 80.58,28.26 78.49,26.16 77.72,26.16 v1(76.96,26.92)
  BOTTOM w0.12: P18.20 119.04,24.34 v1(118.24,25.14)
VOUT1_D13: length 43.2
  SIG_L5 w0.094: v1(81.03,28.7) 81.15,28.7 81.6,28.26 84.39,28.26 84.58,28.45 86.11,28.45 86.49,28.07 89.53,28.07 90.17,27.43 98.04,27.43 99.57,25.91 108.46,25.91 110.49,27.94 116.08,27.94 116.22,28.08 116.22,28.46 116.59,28.83 118.64,28.83 v1(119.13,28.34)
  BOTTOM w0.12: P18.15 v1(119.13,28.34) ; R138.2 v1(81.03,28.7)
VOUT1_D14: length 43.3
  SIG_L5 w0.094: v1(81.03,26.92) 81.15,26.92 81.6,26.48 84.39,26.48 87,23.88 110.74,23.88 113.16,26.29 116.08,26.29 116.31,26.52 116.31,26.91 116.58,27.18 118.69,27.18 v1(119.13,26.74)
  BOTTOM w0.12: P18.17 v1(119.13,26.74) ; R139.2 v1(81.03,26.92)
VOUT1_D15: length 43.3
  SIG_L5 w0.094: v1(81.03,29.59) 81.28,29.59 81.66,29.21 86.11,29.21 86.74,28.57 98.81,28.57 100.84,26.54 103.25,26.54 105.3,28.59 115.08,28.59 115.44,28.96 116.26,28.96 116.52,29.21 117.51,29.21 v1(118.24,29.94)
  BOTTOM w0.12: R140.2 v1(81.03,29.59) ; v1(118.24,29.94) 119.04,29.14 P18.14
VOUT1_D16: length 46.9
  TOP w0.12: R141.2 v1(76.07,26.92)
  SIG_L10 w0.094: v1(76.07,26.92) 76.07,26.8 76.56,26.31 76.56,25.8 76.71,25.65 78.99,25.65 80.71,27.37 84.23,27.37 86.2,25.4 114.68,25.4 115.32,24.77 116.34,24.77 v1(116.71,25.14)
  BOTTOM w0.12: P18.50 115.91,24.34 v1(116.71,25.14)
VOUT1_D17: length 45.8
  TOP w0.12: R142.2 v1(74.3,26.92)
  SIG_L10 w0.094: v1(74.3,26.92) 74.7,26.52 74.7,25.89 75.44,25.15 80.01,25.15 80.45,25.59 85.03,25.59 86.36,24.26 115.1,24.26 v1(115.82,23.54)
  BOTTOM w0.12: P18.51 v1(115.82,23.54)
VOUT1_D18: length 48.8
  TOP w0.12: R143.2 v1(75.18,26.92)
  SIG_L10 w0.094: v1(119.13,23.54) 118.41,24.26 115.44,24.26 114.55,25.15 85.98,25.15 84.65,26.48 80.58,26.48 79.5,25.4 76.07,25.4 75.67,25.8 75.67,26.31 75.18,26.8 v1(75.18,26.92)
  BOTTOM w0.12: P18.21 v1(119.13,23.54)
VOUT1_D19: length 51
  TOP w0.12: R144.2 v1(73.41,26.92)
  SIG_L10 w0.094: v1(73.41,26.92) 73.41,26.8 73.89,26.31 73.89,25.8 74.8,24.89 79.63,24.89 79.82,24.7 85.53,24.7 86.36,23.88 114.68,23.88 115.44,23.11 116.08,23.11 116.31,23.35 116.31,23.73 116.59,24 117.77,24 v1(118.24,23.54)
  BOTTOM w0.12: v1(118.24,23.54) 119.04,22.74 P18.22
VOUT1_D20: length 42.2
  SIG_L5 w0.094: v1(119.13,25.14) 118.12,24.13 113.54,24.13 112.27,22.86 86.49,22.86 84.65,24.7 81.6,24.7 81.15,25.15 v1(81.03,25.15)
  BOTTOM w0.12: P18.19 v1(119.13,25.14) ; R145.2 v1(81.03,25.15)
VOUT1_D21: length 52.1
  TOP w0.12: R146.2 v1(71.63,26.92)
  SIG_L10 w0.094: v1(71.63,26.92) 71.63,26.8 72.03,26.39 72.03,25.89 73.53,24.38 79.12,24.38 80.52,22.99 114.55,22.99 114.94,22.61 118.46,22.61 v1(119.13,21.94)
  BOTTOM w0.12: P18.23 v1(119.13,21.94)
VOUT1_D22: length 50.2
  TOP w0.12: R147.2 v1(72.52,26.92)
  SIG_L10 w0.094: v1(72.52,26.92) 72.52,26.8 72.92,26.39 72.92,25.89 74.17,24.64 79.5,24.64 80.33,23.81 86.04,23.81 86.36,23.5 114.55,23.5 115.19,22.86 116.46,22.86 116.71,23.11 v1(116.71,23.54)
  BOTTOM w0.12: P18.52 115.91,22.74 v1(116.71,23.54)
VOUT1_D23: length 55.6
  TOP w0.12: R148.2 v1(69.85,26.92)
  SIG_L10 w0.094: v1(118.24,21.94) 117.76,21.46 115.06,21.46 114.05,22.48 86.23,22.48 84.96,21.21 80.65,21.21 80.26,21.59 77.22,21.59 74.93,23.88 72.32,23.88 69.85,26.35 v1(69.85,26.92)
  BOTTOM w0.12: P18.24 119.04,21.14 118.24,21.94 v1(118.24,21.94)
VOUT1_DE: length 50.3
  TOP w0.12: R150.2 v1(70.74,26.92)
  SIG_L10 w0.094: v1(70.74,26.92) 70.74,26.29 72.9,24.13 75.18,24.13 77.34,21.97 85.09,21.97 85.89,22.77 114.27,22.77 115.09,21.94 v1(115.82,21.94)
  BOTTOM w0.12: P18.53 v1(115.82,21.94)
VOUT1_HSYNC: length 42.2
  SIG_L5 w0.094: v1(81.03,23.37) 81.47,22.92 81.98,22.92 84.07,20.83 109.35,20.83 110.36,19.81 114.43,19.81 114.94,19.3 118.56,19.3 v1(119.13,18.74)
  BOTTOM w0.12: P18.27 v1(119.13,18.74) ; R152.2 v1(81.03,23.37)
VOUT1_RD0: length 19.3
  TOP w0.12: U11.F11 v2(70.59,33.61)
  SIG_L5 w0.094: v2(70.59,33.61) 70.21,33.23 70.21,30.88 73.41,27.69 77.72,27.69 79.88,25.53 79.88,24.64 80.71,23.81 81.22,23.81 81.66,23.37 v1(81.79,23.37)
  BOTTOM w0.12: R124.1 v1(81.79,23.37)
VOUT1_RD1: length 20.5
  TOP w0.12: U11.G10 v2(71.39,34.41)
  GND_L9 w0.094: v2(71.39,34.41) 71.64,34.41 72.04,34 72.42,34 72.63,33.79 72.63,30.23 73.81,29.05 73.81,25.98 74.52,25.27 78.11,25.27 80.45,22.92 81.34,22.92 v1(81.79,22.48)
  BOTTOM w0.12: R125.1 v1(81.79,22.48)
VOUT1_RD2: length 17.9
  TOP w0.12: U11.F10 v2(71.39,33.61)
  SIG_L5 w0.094: v1(81.79,24.26) 81.66,24.26 81.22,24.7 80.58,24.7 80.14,25.15 80.14,25.65 77.85,27.94 74.04,27.94 70.99,30.99 70.99,33.21 v2(71.39,33.61)
  BOTTOM w0.12: R126.1 v1(81.79,24.26)
VOUT1_RD3: length 21.6
  TOP w0.12: U11.G11 v2(70.59,34.41)
  GND_L9 w0.094: v1(81.79,21.59) 81.34,22.03 80.84,22.03 77.98,24.89 74.02,24.89 72.95,25.96 72.95,29.41 71.76,30.6 71.76,33.77 71.54,34 71.26,34 70.85,34.41 v2(70.59,34.41)
  BOTTOM w0.12: R127.1 v1(81.79,21.59)
VOUT1_RD4: length 14.7
  TOP w0.12: U11.E9 v2(72.19,32.81)
  SIG_L5 w0.094: v1(81.79,26.04) 81.66,26.04 81.22,26.48 80.58,26.48 78.61,28.45 74.68,28.45 72.56,30.56 72.56,32.43 v2(72.19,32.81)
  BOTTOM w0.12: R128.1 v1(81.79,26.04)
VOUT1_RD5: length 16.5
  TOP w0.12: U11.F9 v2(72.19,33.61)
  SIG_L5 w0.094: v1(81.79,25.15) 81.66,25.15 81.22,25.59 80.58,25.59 77.98,28.19 74.42,28.19 71.76,30.85 71.76,33.18 v2(72.19,33.61)
  BOTTOM w0.12: R129.1 v1(81.79,25.15)
VOUT1_RD6: length 13.4
  TOP w0.12: U11.F8 v2(72.99,33.61)
  SIG_L5 w0.094: v2(72.99,33.61) 73.41,33.19 73.88,33.19 73.88,33.18 73.94,33.18 74.16,32.96 74.16,32.69 74.43,32.43 74.76,32.43 75.01,32.18 75.01,30.25 76.05,29.21 80.52,29.21 80.58,29.15 81.22,29.15 81.66,28.7 v1(81.79,28.7)
  BOTTOM w0.12: R130.1 v1(81.79,28.7)
VOUT1_RD7: length 12.6
  TOP w0.12: U11.E7 v2(73.79,32.81)
  SIG_L5 w0.094: v1(81.79,27.81) 81.66,27.81 81.22,28.26 80.71,28.26 80.01,28.96 75.77,28.96 74.74,29.98 74.39,29.98 74.17,30.2 74.17,32.26 73.79,32.64 v2(73.79,32.81)
  BOTTOM w0.12: R131.1 v1(81.79,27.81)
VOUT1_RD8: length 13.8
  TOP w0.12: U11.E8 v2(72.99,32.81)
  SIG_L5 w0.094: v2(72.99,32.81) 73.41,32.39 73.41,30.1 74.8,28.7 79.38,28.7 80.71,27.37 81.22,27.37 81.66,26.92 v1(81.79,26.92)
  BOTTOM w0.12: R132.1 v1(81.79,26.92)
VOUT1_RD9: length 13.8
  TOP w0.12: U11.D9 v2(72.19,32.01)
  BOTTOM w0.12: R133.1 78.23,25.43 78.23,27.43 77.47,28.19 73.79,28.19 71.79,30.19 71.79,31.53 72.19,31.93 v2(72.19,32.01)
VOUT1_RD10: length 9.6
  TOP w0.12: U11.D7 v2(73.79,32.01)
  BOTTOM w0.12: v2(73.79,32.01) 73.39,31.61 73.39,30.12 74.3,29.21 74.42,29.21 74.42,29.21 78.01,29.21 78.76,28.46 78.77,28.46 R134.1
VOUT1_RD11: length 11.7
  TOP w0.12: U11.D8 v2(72.99,32.01)
  BOTTOM w0.12: v2(72.99,32.01) 72.59,31.61 72.59,30.16 74.04,28.7 77.72,28.7 78.74,27.69 78.74,26.7 R135.1
VOUT1_RD12: length 2.6
  TOP w0.12: R136.1 76.31,29.19 75.96,29.19 75.15,30.01 U11.A5
VOUT1_RD13: length 6.9
  TOP w0.12: U11.C6 v2(74.59,31.21)
  BOTTOM w0.12: v2(74.59,31.21) 74.99,30.81 74.99,30.24 75.22,30.01 77.95,30.01 78.19,29.77 78.19,29.44 78.92,28.7 R138.1
VOUT1_RD14: length 9.7
  TOP w0.12: U11.C8 v2(72.99,31.21)
  BOTTOM w0.12: v2(72.99,31.21) 72.99,30.14 74.17,28.96 77.88,28.96 78.99,27.85 78.99,27.34 R139.1
VOUT1_RD15: length 7.7
  TOP w0.12: U11.C7 v2(73.79,31.21)
  BOTTOM w0.12: v2(73.79,31.21) 73.88,31.21 74.28,31.61 75.55,31.61 75.79,31.37 75.79,31.04 76.02,30.81 78.8,30.81 79.41,30.19 R140.1
VOUT1_RD16: length 4
  TOP w0.12: U11.B7 73.79,30.4 73.79,29.85 74.43,29.21 75.44,29.21 76.07,28.57 R141.1
VOUT1_RD17: length 3
  TOP w0.12: R142.1 74.3,28.57 72.99,29.88 72.99,30.41 U11.B8
VOUT1_RD18: length 2.5
  TOP w0.12: U11.A7 73.39,29.87 74.29,28.96 74.76,28.96 R143.1
VOUT1_RD19: length 1.8
  TOP w0.12: U11.A8 72.59,29.36 R144.1
VOUT1_RD20: length 11.8
  TOP w0.12: U11.C9 v2(72.19,31.21)
  BOTTOM w0.12: R145.1 78.49,26.07 78.49,27.56 77.6,28.45 73.91,28.45 72.19,30.18 v2(72.19,31.21)
VOUT1_RD21: length 1.5
  TOP w0.12: U11.A9 71.79,28.7 R146.1
VOUT1_RD22: length 2.6
  TOP w0.12: R147.1 72.52,28.96 72.19,29.29 72.19,30.41 U11.B9
VOUT1_RD23: length 1.9
  TOP w0.12: R148.1 70.99,29.68 U11.A10
VOUT1_RDCLK: length 19.3
  TOP w0.12: U11.D11 v2(70.59,32.01)
  BOTTOM w0.12: v2(70.59,32.01) 70.19,31.61 70.19,31.03 72.04,29.18 72.04,26.05 72.39,25.7 72.39,22.1 72.9,21.59 78.74,21.59 78.99,21.84 78.99,22.06 R149.1
VOUT1_RDE: length 2.7
  TOP w0.12: U11.B10 71.39,30.41 71.39,29.22 70.74,28.57 R150.1
VOUT1_RHSYNC: length 17.8
  TOP w0.12: U11.C11 v2(70.59,31.21)
  BOTTOM w0.12: v2(70.59,31.21) 70.59,31.01 73.82,27.78 73.82,25.99 73.66,25.83 73.66,22.35 74.17,21.84 78.49,21.84 78.74,22.1 78.74,22.73 79.38,23.37 R152.1
VOUT1_RVSYNC: length 21.8
  TOP w0.12: U11.E11 v2(70.59,32.81)
  BOTTOM w0.12: R153.1 79.15,21.34 71.88,21.34 71.12,22.1 71.12,25.96 71.15,25.99 71.15,29.68 70.03,30.81 69.57,30.81 69.39,30.99 69.39,32.17 69.62,32.41 70.19,32.41 v2(70.59,32.81)
VOUT1_VSYNC: length 42.7
  SIG_L5 w0.094: v1(118.24,18.74) 117.78,18.29 114.68,18.29 113.67,19.3 110.11,19.3 109.09,20.32 88.52,20.32 87.88,19.68 82.93,19.68 v1(81.03,21.59)
  BOTTOM w0.12: P18.28 119.04,17.94 v1(118.24,18.74) ; R153.2 v1(81.03,21.59)
VTT: length 4.6
  TOP w0.254: U27.3 31.83,20.95 32.22,21.35 C398.1
  TOP w0.381: C398.1 v1(32.89,21.46) ; Q6.3 32.89,16.99 v1(32.89,17.65) ; R289.1 v1(32.89,22.35)
VTT_PGOOD: length 1.2
  TOP w0.254: U27.9 25.88,20.45 R286.2
VTT_TRAN: length 4.3
  TOP w0.254: R335.2 30.19,17.02 ; 30.19,17.02 Q5.3 ; 30.19,17.02 30.73,17.02 Q6.1
VUSB_3V3: length 7
  TOP w0.254: v2(70.99,70.41) U5.B9 ; v2(69.79,46.41) U11.AA12 v2(69.79,45.61) U11.Y12
  BOTTOM w0.254: C18.2 72.5,70.41 v2(70.99,70.41) ; v2(69.79,45.61) 69.47,45.92 C236.1 69.47,46.09 v2(69.79,46.41)
  BOTTOM w0.381: C238.1 80.17,46.26 C237.1 v1(79.5,47.24)
  vias: v1(77.6,67.56)
WAKEUP1: length 6.5
  TOP w0.12: U11.AC17 v2(64.99,48.01)
  BOTTOM w0.12: R50.1 63.79,53.09 63.79,48.64 64.02,48.41 64.59,48.41 v2(64.99,48.01)
WAKEUP2: length 38.1
  TOP w0.12: U11.AB16 v2(65.79,47.21) ; v2(39.38,60.01) 40.35,60.98 R51.1
  INT_L3 w0.094: v2(39.38,60.01) 38.99,60.4 38.99,61.21 39.5,61.72 51.69,61.72 58.61,54.8 58.99,54.8 61.36,52.43 61.36,51.89 61.68,51.58 61.94,51.58 62.21,51.32 62.21,51.05 62.46,50.8 62.72,50.8 63.76,49.76 63.76,49.39 63.97,49.18 64.36,49.18 64.61,48.93 64.61,48.65 64.83,48.43 65.11,48.43 65.41,48.13 65.41,47.59 v2(65.79,47.21)
ZQ1_HI: length 2.1
  TOP w0.12: v2(39.38,42.41) U24.L8
  BOTTOM w0.12: R275.1 39.78,41.41 39.78,42.01 v2(39.38,42.41)
ZQ1_LO: length 2.3
  TOP w0.12: v2(39.38,53.61) U23.L8
  BOTTOM w0.12: v2(39.38,53.61) 39.78,53.21 39.78,52.61 R276.1
ZQ2_HI: length 2.3
  TOP w0.12: v2(39.38,31.2) U26.L8
  BOTTOM w0.12: R278.1 39.78,30.21 39.78,30.8 v2(39.38,31.2)
ZQ2_LO: length 2.3
  TOP w0.12: v2(39.38,20) U25.L8
  BOTTOM w0.12: R277.1 39.78,19 39.78,19.6 v2(39.38,20)
N23410845: length 61.9
  TOP w0.12: U11.E23 v2(60.19,32.81)
  INT_L3 w0.094: v1(81.79,29.59) 83.16,30.96 83.16,51.34 80.52,53.98 80.52,57.53 80.9,57.91 80.9,60.13 v1(81.41,60.64)
  SIG_L8 w0.094: v1(81.79,29.59) 82.17,29.21 82.17,28.57 81.92,28.32 79.88,28.32 79.25,27.69 69.09,27.69 67.06,29.72 67.06,32.07 66.74,32.38 60.83,32.38 60.41,32.81 v2(60.19,32.81)
  BOTTOM w0.12: v1(81.41,60.64) U10.4 ; v2(60.19,32.81) 60.5,32.49 C98.2
N23730763: length 12.4
  TOP w0.254: U11.N16 v2(65.79,39.21) ; U11.N16 v2(65.79,40.01) U11.P16 v2(66.59,40.01) ; U11.N16 v2(66.59,40.01) ; U11.P15 v2(66.59,40.01) ; U11.P14 v2(68.19,40.01) ; v2(70.59,39.21) U11.N11 v2(69.79,39.21) U11.N12 ; U11.M14 v2(68.19,38.41) ; U11.R17 v2(64.99,41.61) ; U11.R14 v2(68.19,41.61)
  BOTTOM w0.254: v2(68.19,40.01) 67.87,40.32 C199.1 ; C198.1 U11.R17 v2(64.99,41.61) ; v2(66.59,40.01) 66.9,40.32 C203.1 ; v2(69.79,39.21) 69.39,39.6 C200.1
  BOTTOM w0.381: C197.1 62.13,53.12 L10.3 62.59,52.66 v2(62.59,52.01)
N24165486: length 5.3
  TOP w0.254: v2(69.79,44.81) U11.W12 v2(68.99,44.01) U11.V13
  BOTTOM w0.254: C201.1 68.67,43.69 v2(68.99,44.01) U11.W12 C204.1 69.47,44.49 v2(69.79,44.81)
  BOTTOM w0.381: L11.1 v1(77.47,55.26) 77.71,55.5 C202.1
N26024435: length 7.9
  TOP w0.254: U11.AA17 v2(64.99,45.61) U11.Y17 ; U11.AA17 v2(64.99,46.41) ; U11.AA17 v2(65.79,46.41) U11.AA16 ; U11.W14 v3(68.19,44.81)
  BOTTOM w0.254: v2(64.99,46.41) 64.59,46.01 C498.1 ; v2(65.79,46.41) 65.47,46.09 C499.1 U11.AA17 v2(64.99,45.61)
  BOTTOM w0.381: C497.1 73.29,55.5 73.53,55.26 L24.1 v1(75.18,55.26)
N28155188: length 11.8
  TOP w0.12: U11.K14 v2(68.19,36.81)
  INT_L3 w0.094: TP6.1 68.07,28.19 69.13,29.25 69.36,29.49 69.36,36.17 69.09,36.45 68.54,36.45 v2(68.19,36.81)
N28613451: length 5.6
  TOP w0.12: U5.E6 v2(68.59,73.61)
  BOTTOM w0.12: v2(68.59,73.61) 68.2,74 68.2,75.35 67.95,75.6 66.83,75.6 66.63,75.4 R319.2 R318.2
N28614009: length 8.8
  TOP w0.12: U5.E5 v2(68.59,74.41)
  BOTTOM w0.12: R322.2 70.19,79.57 70.07,79.45 70.07,78.74 69.95,78.62 R323.2 69.27,78.27 69.27,78.11 68.98,77.82 68.98,74.8 v2(68.59,74.41) 68.59,74.29 69,73.88 69,73.45 69.23,73.22 69.24,73.22 R433.1
N28826254: length 1.2
  TOP w0.12: R398.2 81.43,85.34 U33.9
N28826261: length 1.2
  TOP w0.12: R399.2 81.44,84.84 U33.8
N29245750: length 1.7
  TOP w0.12: U11.AE14 v2(68.19,49.61)
  BOTTOM w0.12: v2(68.19,49.61) 68.97,50.39 R422.1
N29286052: length 9.5
  BOTTOM w0.12: 79.76,65.91 79.76,65.91 U34.3 ; 79.76,65.91 80.64,65.91 80.76,66.03 U34.1 80.76,67.68 81.44,68.36 R405.2 ; 79.76,65.91 79.12,65.91 78.49,65.28 78.49,63.75 78.12,63.39 U9.3
N29286254: length 3.2
  BOTTOM w0.12: U34.7 80.26,69.08 80.01,68.83 78.99,68.83 78.52,68.36 C476.1
N29286257: length 2.7
  BOTTOM w0.12: R404.1 C476.2 78.45,69.31 78.94,69.8 U34.5 U34.6
N29321384: length 11.5
  SIG_L8 w0.094: v1(90.17,9.78) 94.07,5.88 v1(97.32,5.88)
  BOTTOM w0.12: R31.2 v1(90.17,9.78) ; v1(97.32,5.88) R409.1 C495.1
N29512994: length 33.8
  TOP w0.12: R239.2 v1(112.65,65.53)
  INT_L3 w0.094: v1(112.65,65.53) 112.65,89.38 112.12,89.92 112.12,95.89 J3.2
N29513031: length 29
  TOP w0.12: R182.2 v1(122.3,70.61)
  INT_L3 w0.094: J4.2 114.81,93.5 114.81,89.41 121.79,82.42 121.79,71.12 v1(122.3,70.61)
N29513057: length 28.5
  TOP w0.12: R187.2 v1(122.3,68.58)
  INT_L3 w0.094: v1(122.3,68.58) 121.41,69.47 121.41,82.3 113.54,90.17 J6.2
N29735394: length 1.8
  TOP w0.12: U17.41 92.46,34.3 v1(92.46,35.31)
  BOTTOM w0.12: R328.1 v1(92.46,35.31)
N29868563: length 2.7
  BOTTOM w0.12: Q7.1 100.24,6.44 99.86,6.82 R410.1 R409.2
N29882506: length 7.2
  BOTTOM w0.12: U42.2 103.63,8.51 104.01,8.13 104.3,8.13 R408.2 104.39,5.84 102.78,4.23 Q7.3
N29907779: length 2.7
  BOTTOM w0.12: U42.4 100.09,7.86 99.92,8.03 R415.2 R413.1
N29975844: length 1.6
  TOP w0.12: U5.C1 69.79,77.48 70.07,77.76 v2(70.07,78.09)
  BOTTOM w0.12: v2(70.07,78.09) 70.07,77.61 C496.1
N30391816: length 4.8
  BOTTOM w0.12: Q9.1 U43.2 81.41,71.75 80.99,71.34 R423.2 R430.1
N30391875: length 12.8
  BOTTOM w0.12: R425.1 82.55,75.82 83.44,74.93 83.44,73.15 ; 83.44,73.15 U43.1 83.44,71.09 R430.2 ; 83.44,73.15 78.87,73.15 78.61,72.9 78.61,71.88 78.2,71.47 R424.2
N30606654: length 5
  BOTTOM w0.12: Q8.1 U35.2 51.18,76.07 51.6,76.49 R418.2 R429.1
N30606697: length 14.3
  BOTTOM w0.12: R420.1 49.06,74.42 ; 49.06,74.42 49.06,75.31 U35.1 49.06,75.49 R429.2 ; 49.06,74.42 55.63,74.42 55.88,74.68 55.88,76.67 R419.2
N30851376: length 1.8
  TOP w0.12: v1(100.59,66.76) 100.87,67.04 U15.18
  BOTTOM w0.12: v1(100.59,66.76) 101.33,66.76 R478.2
N31260694: length 2.5
  BOTTOM w0.12: R68.1 103.86,101.98 104.24,102.36 P5.28
N31260700: length 3.7
  BOTTOM w0.12: R69.2 96.72,101.85 96.22,102.36 95.63,102.36 P5.30
N31260959: length 1.7
  BOTTOM w0.12: R98.2 P5.34
N31261983: length 1.6
  BOTTOM w0.12: P5.32 103.2,78.69 R97.1
N31304297: length 1.8
  TOP w0.12: U14.18 87.12,66.74 v1(86.84,66.47)
  BOTTOM w0.12: v1(86.84,66.47) 87.6,66.47 R477.2
N31316106: length 1.3
  TOP w0.12: R479.2 86.64,69.29 87.19,68.74 U14.14
N31316228: length 1.3
  TOP w0.12: R480.2 100.82,69.04 U15.14

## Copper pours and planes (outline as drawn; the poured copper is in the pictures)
3V3_CDC on BOTTOM: 27.94,53.59 27.05,52.7 27.05,49.28 27.18,49.15 27.94,49.15 28.19,48.9 28.19,47.88 28.32,47.75 29.08,47.75 29.21,47.62 29.21,47.37 29.08,47.24 27.69,47.24 27.56,47.37 27.56,48.51 27.43,48.64 25.4,48.64 25.15,48.9 25.15,55.12 25.4,55.37 27.69,55.37 27.94,55.12
5V0 on TOP: 72.01,70.87 71.37,70.87 71.25,70.74 71.25,69.98 71.75,69.47 73.41,69.47 73.66,69.72 73.66,72.52 74.42,73.28 74.42,73.53 74.3,73.66 71.63,73.66 71.25,73.28 71.25,73.03 72.14,72.14 72.14,70.99
5V0 on SIG_L5: 59.69,73.41 62.74,73.41 63.12,73.79 63.12,74.93 63.37,75.18 70.48,75.18 70.87,75.56 70.87,82.42 70.48,82.8 61.59,82.8 61.34,83.06 61.34,86.23 60.96,86.61 59.94,86.61 59.69,86.87 59.69,105.71 59.94,105.97 64.39,105.97 64.64,105.71 64.64,103.58 65.41,102.82 66.4,102.82 67.31,101.9 67.31,87.88 67.56,87.63 74.68,87.63 74.93,87.38 74.93,69.6 74.68,69.34 71.5,69.34 71.25,69.6 65.18,69.6 64.92,69.85 64.92,70.51 64.72,70.71 58.55,70.71 57.45,71.81 56.41,71.81 55.88,72.34 55.88,74.42 56.13,74.68 58.42,74.68
5V0 on PWR_L6: outline of 90 points within 14.1,1.52 123.06,106.05
5V0_TAP on TOP: 38.61,71.88 38.1,72.39 33.78,72.39 33.02,73.15 33.02,75.18 33.27,75.44 45.72,75.44 46.23,74.93 51.05,74.93 51.31,74.68 51.31,72.64 51.05,72.39 41.91,72.39 41.66,72.14 41.66,67.69 41.4,67.44 38.86,67.44 38.61,67.69
12V on TOP: 29.08,66.42 29.21,66.29 29.21,65.79 29.08,65.66 26.67,65.66 26.54,65.79 26.54,66.8 26.67,66.93 27.18,66.93 27.69,66.42
12V on TOP: 26.67,80.26 26.8,80.14 26.8,79.63 26.67,79.5 25.27,79.5 24.77,78.99 24.26,78.99 24.13,79.12 24.13,80.64 24.26,80.77 24.77,80.77 25.27,80.26
12V on TOP: 100.2,44.2 100.33,44.07 100.33,43.56 100.2,43.43 98.81,43.43 98.3,42.93 97.79,42.93 97.66,43.05 97.66,44.58 97.79,44.7 98.3,44.7 98.81,44.2
12V on BOTTOM: 25.91,94.34 26.54,93.71 26.54,90.05 26.2,89.71 21.63,89.71 20.96,90.39 20.96,93.34 21.95,94.34
12V on BOTTOM: 32.39,69.34 32.64,69.09 32.64,67.31 32.39,67.06 30.86,67.06 30.35,66.55 28.45,66.55 28.32,66.42 28.32,65.91 28.19,65.79 27.81,65.79 27.69,65.66 26.67,65.66 26.54,65.79 26.54,69.09 26.8,69.34
12V on BOTTOM: 103.5,47.12 103.76,46.86 103.76,45.09 103.5,44.83 101.98,44.83 101.73,44.58 101.73,43.31 101.47,43.05 98.43,43.05 97.66,43.18 97.66,46.86 97.92,47.12
12V on BOTTOM: 32.51,83.31 32.89,82.93 32.89,81.92 31.88,80.9 28.45,80.9 27.94,80.39 26.04,80.39 25.91,80.26 25.91,79.76 25.78,79.63 25.4,79.63 24.77,78.99 24.26,78.99 24.13,79.12 24.13,82.93 24.51,83.31
12V on PWR_L6: outline of 98 points within 19.05,40.13 123.06,106.05 ; 2 cut-outs
12V_MAIN on BOTTOM: 38.02,87.08 37.29,87.81 34.81,87.81 32.08,90.54 28.7,90.54 28.39,90.85 28.39,94.21 28.54,94.36 31.99,94.36 31.99,94.36 33.76,94.36 34.8,93.32 36.2,93.32 36.68,93.8 41.66,93.8 43.77,91.69 43.77,88.34 42.51,87.08
GND on TOP: 30.48,63.12 30.48,67.82 30.23,68.07 28.32,68.07 28.07,68.33 28.07,75.18 28.32,75.44 31.5,75.44 31.75,75.18 31.75,73.41 32.51,72.64 32.51,69.6 33.02,69.09 33.02,66.67 33.27,66.42 36.96,66.42 37.08,66.29 37.08,65.79 36.96,65.66 33.27,65.66 33.02,65.41 33.02,63.12 33.27,62.87 34.54,62.87 34.67,62.74 34.67,62.1 34.54,61.98 28.96,61.98 28.83,62.1 28.83,62.74 28.96,62.87 30.23,62.87
